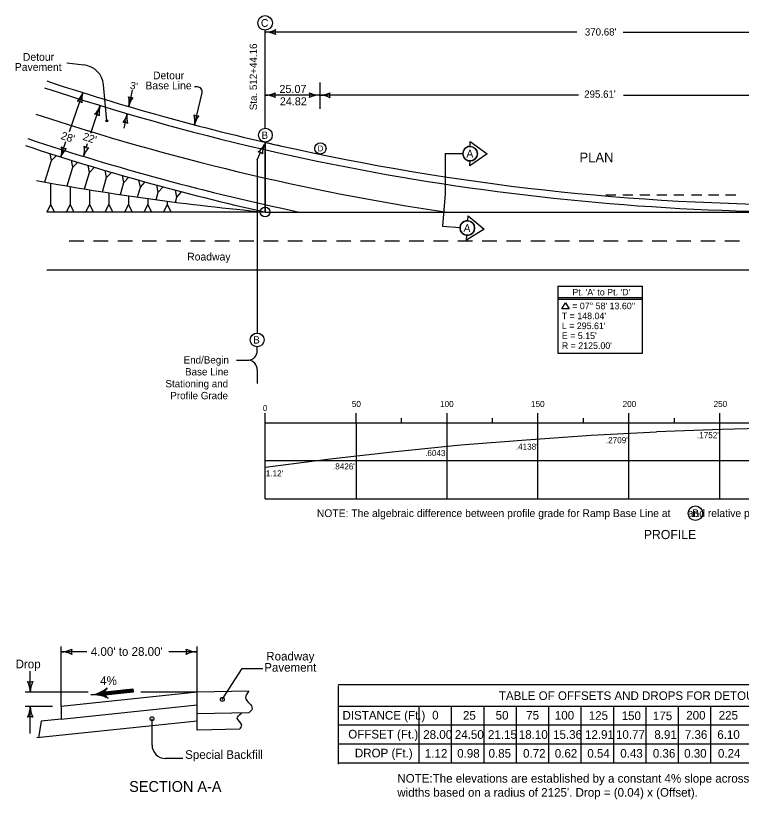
# Model space of a CAD drawing. Extents: x 10133 to 81668, y 4099 to 11018.
# Drawn here: x 13872 to 15616, y 4140 to 6024 of the extents above; entities that cross this region are included whole.
import ezdxf

# ---------------------------------------------------------------- set-up
doc = ezdxf.new("R2010")
doc.units = 0
for name, color, linetype in [('Default', 7, 'Continuous'), ('dsnCellElements', 7, 'Continuous'), ('Level 1', 7, 'Continuous'), ('Level 10', 7, 'Continuous'), ('Level 12', 7, 'Continuous'), ('Level 4', 7, 'Continuous'), ('Level 5', 7, 'Continuous'), ('SheetAddendum', 7, 'Continuous'), ('ShtPlotIdentification', 7, 'Continuous')]:
    doc.layers.add(name, color=color, linetype=linetype)

msp = doc.modelspace()

# ---------------------------------------------------------------- linework, layer by layer
at = {"layer": 'Default'}
for p, q in [((14471.7, 5551.9), (14471.7, 5719.6)), ((14471.7, 5719.6), (14471.7, 5551.9)), ((14471.7, 5551.9), (16078.7, 5551.9)), ((14471.7, 5551.9), (16078.7, 5551.9))]:
    msp.add_line(p, q, dxfattribs=at)
for centre, radius, start, end in [((15786.9, 11406.1), 5836.7, 251.62748, 257.33821), ((15786.9, 11406.1), 5854, 251.62748, 272.85748), ((15786.9, 11406.1), 5920.4, 251.62748, 261.4196), ((15786.9, 11406.1), 5982.7, 251.62748, 258.10097), ((15786.9, 11406.1), 6000.1, 251.62748, 257.33821), ((15786.9, 11406.1), 5836.7, 256.97753, 257.33821), ((15786.9, 11406.1), 5836.7, 257.33821, 270), ((15786.9, 11406.1), 5836.7, 257.33821, 270), ((15002.9, 11433.9), 5905.9, 259.45431, 264.83954)]:
    msp.add_arc(centre, radius, start, end, dxfattribs=at)
at = {"layer": 'dsnCellElements'}
for p, q in [((16087.1, 4415.5), (14647.3, 4415.5)), ((14647.3, 4413.3), (14647.3, 4225.1)), ((16087.1, 4363.6), (14647.3, 4363.6)), ((14841.2, 4363.6), (14841.2, 4227.3)), ((14919, 4363.6), (14919, 4363.6)), ((14919, 4363.6), (14919, 4227.3)), ((14919.3, 4363.6), (14919.3, 4363.6)), ((14919.4, 4363.6), (14919.4, 4363.6)), ((14919.6, 4363.6), (14919.6, 4363.6)), ((14996.9, 4363.6), (14996.9, 4227.3)), ((14996.9, 4363.6), (14996.9, 4363.6)), ((14996.9, 4363.6), (14996.9, 4227.3)), ((14997.1, 4363.6), (14997.1, 4363.6)), ((14997.3, 4363.6), (14997.3, 4363.6)), ((14997.5, 4363.6), (14997.5, 4363.6)), ((15074.8, 4363.6), (15074.8, 4227.3)), ((15152.7, 4363.6), (15152.7, 4227.3)), ((15230.5, 4363.6), (15230.5, 4227.3)), ((15308.4, 4363.6), (15308.4, 4227.3)), ((15386.3, 4363.6), (15386.3, 4227.3)), ((15464.1, 4363.6), (15464.1, 4227.3)), ((15542, 4363.6), (15542, 4227.3)), ((16087.1, 4318.2), (14647.3, 4318.2)), ((16087.1, 4272.8), (14647.3, 4272.8)), ((16087.1, 4227.3), (14647.3, 4227.3))]:
    msp.add_line(p, q, dxfattribs=at)
at = {"layer": 'Level 1'}
for p, q in [((13958.3, 5675.6), (13955.5, 5692.4)), ((13941.9, 5624.1), (13958.3, 5675.6)), ((13958.3, 5675.6), (13970.3, 5687.6)), ((14009.7, 5659.5), (14006.7, 5676.2)), ((14009.7, 5659.5), (14021.6, 5671.6)), ((13995.8, 5614.5), (14009.7, 5659.5)), ((14049.7, 5647.2), (14046.6, 5663.9)), ((14049.7, 5647.2), (14061.5, 5659.4)), ((14090.7, 5635), (14087.5, 5651.7)), ((14037.7, 5607.4), (14049.7, 5647.2)), ((14080.6, 5600.5), (14090.7, 5635)), ((14090.7, 5635), (14102.5, 5647.3)), ((14132.2, 5623), (14128.9, 5639.6)), ((14132.2, 5623), (14143.9, 5635.4)), ((13956.3, 5621.5), (13956.3, 5569.9)), ((14123.9, 5593.8), (14132.2, 5623)), ((14171.8, 5611.8), (14168.3, 5628.5)), ((14171.8, 5611.8), (14183.3, 5624.3)), ((14214.8, 5600), (14211.3, 5616.6)), ((14003, 5613.3), (14003, 5569.9)), ((14049.7, 5605.4), (14049.7, 5569.9)), ((14096.4, 5598), (14096.4, 5569.9)), ((14165, 5587.7), (14171.8, 5611.8)), ((14209.8, 5581.5), (14214.8, 5600)), ((14214.8, 5600), (14226.3, 5612.5)), ((14259.6, 5588), (14255.9, 5604.6)), ((14259.6, 5588), (14271, 5600.7)), ((14143.1, 5590.9), (14143.1, 5569.9)), ((14189.8, 5584.2), (14189.8, 5569.9)), ((14236.5, 5577.9), (14236.5, 5569.9)), ((14256.3, 5575.4), (14259.6, 5588)), ((13956.3, 5569.9), (13946.7, 5551.4)), ((13956.3, 5569.9), (13965.6, 5551.9)), ((14003, 5569.9), (13993.7, 5551.9)), ((14003, 5569.9), (14012.3, 5551.9)), ((14049.7, 5569.9), (14040.4, 5551.9)), ((14049.7, 5569.9), (14059, 5551.9)), ((14096.4, 5569.9), (14086.8, 5551.4)), ((14096.4, 5569.9), (14105.7, 5551.9)), ((14143.1, 5569.9), (14133.8, 5551.9)), ((14143.1, 5569.9), (14152.4, 5551.9)), ((14189.8, 5569.9), (14180.5, 5551.9)), ((14189.8, 5569.9), (14199, 5551.9)), ((14236.5, 5569.9), (14227.2, 5551.9)), ((14236.5, 5569.9), (14245.7, 5551.9))]:
    msp.add_line(p, q, dxfattribs=at)
at = {"layer": 'Level 10'}
for p, q in [((14471.7, 5753.1), (14471.7, 5988.9)), ((14309, 5852.6), (14301.8, 5852.6)), ((14301.8, 5761.5), (14320.3, 5838.1)), ((14471.7, 5719.6), (14471.7, 5720.1)), ((14452.5, 5677.7), (14460.5, 5694.6)), ((14452.5, 5677.7), (14452.5, 5261)), ((15174.7, 5373.4), (15174.7, 5212.7)), ((15174.7, 5373.4), (15378.3, 5373.4)), ((15378.3, 5212.7), (15378.3, 5373.4)), ((15174.7, 5346.3), (15378.3, 5346.3)), ((15174.7, 5342.5), (15378.3, 5342.5)), ((15184.6, 5318.8), (15193.6, 5333.7)), ((15193.6, 5333.7), (15202.5, 5318.8)), ((15202.5, 5318.8), (15184.6, 5318.8)), ((14452.5, 5218.9), (14452.5, 5228)), ((15174.7, 5212.7), (15378.3, 5212.7)), ((14402.5, 5195.7), (14432.1, 5195.7)), ((14452.5, 5172.5), (14452.5, 5139.8)), ((13981.3, 4363.3), (13981.3, 4507.3)), ((14308.1, 4397.5), (14308.1, 4507.3)), ((14199.8, 4333.9), (14199.8, 4270.7)), ((14273.7, 4238.3), (14232.3, 4238.3))]:
    msp.add_line(p, q, dxfattribs=at)
for centre, radius in [((14471.7, 6006.4), 17.5), ((14091.5, 5770.9), 2.42), ((14091.5, 5770.9), 2.05), ((14091.5, 5770.9), 1.71), ((14091.5, 5770.9), 1.32), ((14091.5, 5770.9), 1.05), ((14091.5, 5770.9), 0.874), ((14091.5, 5770.9), 0.683), ((14091.5, 5770.9), 0.505), ((14091.5, 5770.9), 0.313), ((14091.5, 5770.9), 0.149), ((14472.3, 5736.6), 16.5), ((14604.6, 5704.7), 13.4), ((14471.7, 5551.9), 11.7), ((14452.5, 5244.5), 16.5)]:
    msp.add_circle(centre, radius, dxfattribs=at)
for centre, radius, start, end in [((14309, 5840.9), 11.7, 346.4041, 90), ((14152.2, 5844.7), 18.1, 240.459, 275.9257), ((14098.4, 5815.9), 46.8, 348.1924, 16.2649), ((14189.9, 5796.8), 46.8, 140.1199, 168.1924), ((14094.5, 5797.2), 46.8, 320.1199, 348.1924), ((14186, 5778.1), 46.8, 168.1924, 196.2649), ((14310.5, 5802.2), 19.2, 240.2469, 275.7136), ((14253.3, 5771.8), 49.6, 347.9802, 16.0527), ((14350.3, 5751.2), 49.6, 139.9077, 167.9802), ((14132.2, 5749.3), 18.1, 60.459, 95.9257), ((14426.8, 5734.3), 47.3, 306.4802, 334.5527), ((14512.3, 5693.6), 47.3, 154.5527, 182.6252), ((14452.5, 5678.1), 18.3, 46.8193, 82.286), ((14430.5, 5217.6), 22, 274.0563, 3.2919), ((14430.5, 5173.8), 22, 356.7081, 85.9437), ((14232.3, 4270.7), 32.4, 180, 270)]:
    msp.add_arc(centre, radius, start, end, dxfattribs=at)
at = {"layer": 'Level 12'}
for centre in [(14368.8, 4380.5), (14199.8, 4333.9)]:
    msp.add_circle(centre, 4.6, dxfattribs=at)
at = {"layer": 'Level 4'}
for p, q in [((14904.6, 5692.5), (14903.9, 5595.8)), ((14904.6, 5692.5), (14946.6, 5692.2)), ((14903.9, 5595.8), (14898.1, 5517.8)), ((14898.1, 5517.8), (14940, 5514.7))]:
    msp.add_line(p, q, dxfattribs=at)
for points in [[(14964.2, 5709.6), (14964.3, 5721.2), (15004.9, 5691.8), (14963.9, 5662.9), (14964, 5674.6)], [(14964.2, 5709.6), (14964.2, 5709.6), (14964.2, 5709.6)], [(14958.8, 5530.9), (14959.7, 5542.5), (14998.3, 5510.4), (14955.4, 5484.3), (14956.2, 5496)], [(14958.8, 5530.9), (14958.8, 5530.9), (14958.8, 5530.9)]]:
    msp.add_lwpolyline(points, dxfattribs=at)
for centre, radius in [((14964.1, 5692.1), 17.5), ((14957.5, 5513.4), 17.5), ((15505.5, 4827.9), 17.4)]:
    msp.add_circle(centre, radius, dxfattribs=at)
for centre, start, end in [((14964.1, 5692.1), 89.5971, 269.5988), ((14964.1, 5692.1), 269.5988, 89.5971), ((14957.5, 5513.4), 85.783, 265.7846), ((14957.5, 5513.4), 265.7846, 85.783)]:
    msp.add_arc(centre, 17.5, start, end, dxfattribs=at)
at = {"layer": 'Level 5'}
for p, q in [((15314.7, 5592.6), (15290.2, 5592.6)), ((15355.5, 5592.6), (15331, 5592.6)), ((15396.4, 5592.6), (15371.9, 5592.6)), ((15437.2, 5592.6), (15412.7, 5592.6)), ((15478.1, 5592.6), (15453.6, 5592.6)), ((15520.9, 5592.8), (15496.4, 5592.8)), ((15561.7, 5592.8), (15537.2, 5592.8)), ((15602.6, 5592.8), (15578.1, 5592.8)), ((14455.2, 5551.9), (13946.7, 5551.9)), ((14035.9, 5481.9), (14000.8, 5481.9)), ((14094.2, 5481.9), (14059.2, 5481.9)), ((14152.6, 5481.9), (14117.6, 5481.9)), ((14211, 5481.9), (14175.9, 5481.9)), ((14269.3, 5481.9), (14234.3, 5481.9)), ((14327.7, 5481.9), (14292.7, 5481.9)), ((14386.1, 5481.9), (14351, 5481.9)), ((14444.4, 5481.9), (14409.4, 5481.9)), ((14502.8, 5481.9), (14467.8, 5481.9)), ((14561.2, 5481.9), (14526.1, 5481.9)), ((14619.5, 5481.9), (14584.5, 5481.9)), ((14677.9, 5481.9), (14642.9, 5481.9)), ((14736.3, 5481.9), (14701.2, 5481.9)), ((14794.6, 5481.9), (14759.6, 5481.9)), ((14853, 5481.9), (14818, 5481.9)), ((14911.4, 5481.9), (14876.3, 5481.9)), ((14969.7, 5481.9), (14934.7, 5481.9)), ((15028.1, 5481.9), (14993.1, 5481.9)), ((15086.5, 5481.9), (15051.4, 5481.9)), ((15144.8, 5481.9), (15109.8, 5481.9)), ((15203.2, 5481.9), (15168.2, 5481.9)), ((15261.6, 5481.9), (15226.5, 5481.9)), ((15319.9, 5481.9), (15284.9, 5481.9)), ((15378.3, 5481.9), (15343.3, 5481.9)), ((15436.7, 5481.9), (15401.6, 5481.9)), ((15495, 5481.9), (15460, 5481.9)), ((15553.4, 5481.9), (15518.4, 5481.9)), ((15611.8, 5481.9), (15576.7, 5481.9)), ((16078.7, 5411.9), (13947, 5411.9)), ((14471.5, 4862.5), (14471.5, 5068.1)), ((14690.1, 5045.3), (14690.1, 5068.1)), ((14908.7, 4862.5), (14908.7, 5068.1)), ((15127.3, 4862.5), (15127.3, 5068.1)), ((15345.9, 4862.5), (15345.9, 5068.1)), ((15564.5, 4862.5), (15564.5, 5068.1)), ((14799.4, 5045.3), (14799.4, 5056.7)), ((15018, 5045.3), (15018, 5056.7)), ((15236.6, 5045.3), (15236.6, 5056.7)), ((15455.2, 5045.3), (15455.2, 5056.7)), ((14471.5, 5045.3), (16220.3, 5045.3)), ((14690.1, 5045.3), (14690.1, 4862.5)), ((15725.9, 5033), (15569.1, 5029.2)), ((15098.7, 5004.2), (15255.5, 5015.3)), ((15255.5, 5015.3), (15412.3, 5023.7)), ((15569.1, 5029.2), (15412.3, 5023.7)), ((14785.1, 4976.4), (14941.9, 4992.2)), ((14941.9, 4992.2), (15098.7, 5004.2)), ((14628.3, 4958.8), (14785.1, 4976.4)), ((14471.5, 4938.4), (14628.3, 4958.8)), ((16220.3, 4953.9), (14471.5, 4953.9)), ((14471.5, 4862.5), (16220.3, 4862.5)), ((14368.8, 4380.5), (14416.5, 4454.4)), ((14416.5, 4454.4), (14466, 4454.4)), ((14308.1, 4397.5), (13981.3, 4363.3)), ((14432.7, 4400), (14308.1, 4397.5)), ((14308.1, 4306.6), (14308.1, 4397.5)), ((13981.3, 4333), (14308.1, 4367.2)), ((13981.3, 4363.3), (13981.3, 4333)), ((13981.3, 4333), (13933.1, 4328)), ((14432.6, 4348), (14309.1, 4345.6)), ((14308.1, 4328), (13923.3, 4287.8)), ((13933.1, 4328), (13926.8, 4288.2)), ((14410.3, 4308.6), (14309.9, 4306.6))]:
    msp.add_line(p, q, dxfattribs=at)
msp.add_lwpolyline([(14308.1, 4397.5), (13981.3, 4363.3), (13981.3, 4333), (14308.1, 4367.2)], close=True, dxfattribs=at)
for points in [[(14432.7, 4400), (14424.6, 4384.8), (14440.3, 4358.3), (14432.6, 4348)], [(14410.3, 4308.6), (14415.3, 4319.1), (14404.6, 4334.8), (14414.6, 4347.6)]]:
    msp.add_spline(points, degree=3, dxfattribs=at)
at = {"layer": 'SheetAddendum'}
for p, q in [((15221, 5984.3), (14472.9, 5984.3)), ((15331.7, 5984.3), (16079.7, 5984.3)), ((14036.2, 5905.3), (13995.2, 5909.4)), ((14603.7, 5800.2), (14603.7, 5863.4)), ((14091.5, 5770.9), (14083.4, 5857.7)), ((14152.2, 5844.7), (14144.2, 5806.3)), ((14001.8, 5745.3), (14033.3, 5838.7)), ((14536.2, 5832.8), (14472.4, 5832.8)), ((14601.5, 5832.9), (14536.2, 5832.8)), ((15224.4, 5832.6), (14606.5, 5832.6)), ((15333.2, 5832.9), (15786.1, 5833.3)), ((14052.8, 5741.1), (14073, 5801.7)), ((14132.9, 5753.1), (14136.9, 5771.6)), ((13980.8, 5684.3), (13992.7, 5721.1)), ((14041.3, 5705.1), (14045.2, 5717)), ((14043.2, 4494.8), (13981.3, 4494.8)), ((14308.1, 4494.8), (14240.5, 4494.8)), ((13907.3, 4397.5), (13907.3, 4448.4)), ((14046.7, 4397.5), (13895.4, 4397.5)), ((14086.7, 4398.9), (14086.7, 4398.9)), ((14086.9, 4394.8), (14154.4, 4401.8)), ((14087.5, 4390.9), (14087.5, 4390.9)), ((14307.7, 4397.5), (14173, 4397.5)), ((13961.1, 4363.3), (13895.4, 4363.3)), ((13907.3, 4298.7), (13907.3, 4363.3))]:
    msp.add_line(p, q, dxfattribs=at)
for points in [[(14088, 4403.9), (14085.6, 4399), (14086, 4392.2), (14089, 4386.5), (14078.6, 4389.7), (14066.6, 4391.9), (14063.3, 4392.3), (14071.5, 4394.9), (14083.3, 4400.5), (14086.7, 4402.8), (14086.9, 4388.3), (14068.3, 4392.6), (14085.2, 4399.8), (14085.6, 4389.8), (14072.8, 4393.2), (14083.8, 4397.2), (14084.9, 4391.5), (14076.8, 4393.2), (14082.6, 4395.6), (14083.2, 4392.9), (14080.3, 4393.4)], [(14086.7, 4398.7), (14154, 4405.7), (14154.8, 4398), (14087.5, 4390.9), (14087, 4397.6), (14153.2, 4404.8), (14153.7, 4398.6), (14088.9, 4392.1), (14088.2, 4396.7), (14152.4, 4403.6), (14152.7, 4399.5), (14089.6, 4392.9), (14089.2, 4395.8), (14151.7, 4402.7), (14151.9, 4400.4), (14090.4, 4394)]]:
    msp.add_lwpolyline(points, dxfattribs=at)
for centre, radius, start, end in [((14473, 6035.2), 50.9, 270, 298.0725), ((14515.6, 5984.3), 19.7, 162.2666, 197.7334), ((14473, 5933.4), 50.9, 61.9275, 90), ((14030.9, 5852.8), 52.8, 5.3657, 84.2172), ((13986.1, 5854.3), 49.6, 313.6652, 341.7377), ((14080.4, 5823.2), 49.6, 161.7377, 189.8102), ((14472.4, 5882.4), 49.6, 270, 298.0725), ((14472.4, 5783.2), 49.6, 61.9275, 90), ((14514, 5832.8), 19.2, 162.2666, 197.7334), ((14559.9, 5832.9), 19.2, 342.2666, 17.7333), ((14601.5, 5882.5), 49.6, 241.9275, 270), ((14601.5, 5783.3), 49.6, 90, 118.0725), ((14603.7, 5882.2), 49.6, 270, 298.0725), ((14603.7, 5783), 49.6, 61.9275, 90), ((14645.3, 5832.6), 19.2, 162.2666, 197.7334), ((14020.2, 5799.2), 19.2, 54.0044, 89.4711), ((14027.7, 5822.8), 49.6, 313.6652, 341.7377), ((14122, 5791.7), 49.6, 161.7377, 189.8102), ((14061.8, 5767.8), 19.2, 54.0044, 89.4711), ((13933.7, 5699.8), 49.6, 341.7377, 9.8102), ((13993.8, 5723.8), 19.2, 234.0044, 269.4711), ((13987.9, 5701.5), 49.6, 341.7377, 9.8102), ((14048, 5725.4), 19.2, 234.0044, 269.4711), ((14027.9, 5668.7), 49.6, 133.6652, 161.7377), ((14082.1, 5670.4), 49.6, 133.6652, 161.7377), ((13981.3, 4549.9), 55.2, 270, 298.0725), ((13981.3, 4439.6), 55.2, 61.9275, 90), ((14027.5, 4494.8), 21.3, 162.2666, 197.7334), ((14261.8, 4494.8), 21.3, 342.2667, 17.7334), ((14308.1, 4549.9), 55.2, 241.9275, 270), ((14308.1, 4439.6), 55.2, 90, 118.0725), ((13907.3, 4443.7), 21.3, 252.2667, 287.7334), ((13852.2, 4397.5), 55.2, 0, 28.0725), ((13962.5, 4397.5), 55.2, 151.9275, 180), ((13852.2, 4363.3), 55.2, 331.9275, 0), ((13962.5, 4363.3), 55.2, 180, 208.0725), ((13907.3, 4317.1), 21.3, 72.2666, 107.7334)]:
    msp.add_arc(centre, radius, start, end, dxfattribs=at)
for centre, major_axis, start_param, end_param in [((14041.6, 4474.1), (8.7, -83.2), 0.029395, 0.553518), ((14100.9, 4396.2), (-1.5, 14.6), 0.553526, 2.588067), ((14059, 4307.8), (8.7, -83.2), 2.588074, 3.112197)]:
    msp.add_ellipse(centre, major_axis=major_axis, ratio=0.985299, start_param=start_param, end_param=end_param, dxfattribs=at)
at = {"layer": 'ShtPlotIdentification'}
msp.add_line((14471.7, 5551.9), (14455.2, 5551.9), dxfattribs=at)

# ---------------------------------------------------------------- texts
at = {"layer": 'dsnCellElements'}
for s, height, p in [('TABLE OF OFFSETS AND DROPS FOR DETOUR PAVEMENT', 20.766, (15033.3, 4379)), ('DISTANCE (Ft.)', 20.766, (14657.6, 4331.8)), ('0', 20.7, (14873, 4332.2)), ('25', 20.75, (14947, 4331.6)), ('50', 20.75, (15025.6, 4331.9)), ('75', 20.75, (15099.1, 4331.9)), ('100', 20.75, (15167.9, 4331.9)), ('125', 20.75, (15249.4, 4331.3)), ('150', 20.75, (15328.4, 4330.7)), ('200', 20.75, (15483.6, 4331.9)), ('225', 20.75, (15561.6, 4331.9)), ('175', 20.75, (15403.5, 4330.5)), ('OFFSET (Ft.)', 20.766, (14671.4, 4286.4)), ('28.00', 20.75, (14851.6, 4285.6)), ('24.50', 20.75, (14927.6, 4285.6)), ('21.15', 20.75, (15007.1, 4285.6)), ('18.10', 20.75, (15081.3, 4285.6)), ('15.36', 20.75, (15163.6, 4285.6)), ('12.91', 20.75, (15240.4, 4285.6)), ('10.77', 20.75, (15314.7, 4285.6)), ('8.91', 20.75, (15406.9, 4285.6)), ('7.36', 20.75, (15480.2, 4285.6)), ('6.10', 20.75, (15558.2, 4285.6)), ('DROP (Ft.)', 20.77, (14687.3, 4241)), ('1.12', 20.75, (14855.6, 4240.2)), ('0.98', 20.75, (14933.2, 4240.3)), ('0.85', 20.75, (15008.6, 4240.3)), ('0.72', 20.75, (15091.4, 4240.3)), ('0.62', 20.75, (15167.7, 4240.3)), ('0.54', 20.75, (15245.9, 4240.3)), ('0.43', 20.75, (15325.1, 4240.3)), ('0.36', 20.75, (15403.4, 4240.3)), ('0.30', 20.75, (15478.6, 4240.3)), ('0.24', 20.75, (15559.8, 4240.3))]:
    msp.add_text(s, height=height, dxfattribs=at).set_placement(p)
at = {"layer": 'Level 10'}
for s, height, p in [('C', 18.7, (14461.5, 5997)), ("370.68'", 17.43, (15240, 5976.1)), ('Detour ', 18.68, (13889.5, 5915.4)), ('Pavement', 18.68, (13870.2, 5891.2)), ('Detour', 18.68, (14202.2, 5870.9)), ('Base Line', 18.68, (14184, 5846.7)), ('25.07', 19.36, (14506.1, 5838)), ("295.61'", 17.42, (15238.4, 5826.6)), ('24.82', 19.36, (14507, 5808.3)), ('B', 17.6, (14463, 5727.8)), ('D', 14.3, (14598, 5697.5)), ('PLAN', 23.35, (15227.1, 5671.5)), ('Roadway               ', 18.677, (14284.4, 5435.4)), ("Pt. 'A' to Pt. 'D'", 15.889, (15209.9, 5351.3)), ("= 07° 58' 13.60''", 15.889, (15209.5, 5318.3)), ("T = 148.04'", 15.889, (15184.6, 5294.3)), ("L = 295.61'", 15.889, (15184.6, 5270.4)), ("E = 5.15'", 15.89, (15184.6, 5246.6)), ('B', 17.6, (14443.1, 5235.7)), ("R = 2125.00'", 15.889, (15184.6, 5222.8)), ('End/Begin', 17.6, (14275.9, 5187.7)), ('Base Line', 17.6, (14279.3, 5159.1)), ('Stationing and', 17.603, (14232.2, 5130.5)), ('Profile Grade', 17.603, (14243.8, 5101.9)), ('0', 14.6, (14466.3, 5073.4)), ('50', 14.62, (14680.1, 5083.2)), ('100', 14.62, (14892, 5083.2)), ('150', 14.62, (15110.6, 5083.2)), ('200', 14.62, (15330.7, 5083.2)), ('250', 14.62, (15549.3, 5083.2)), (".2709'", 14.62, (15290.6, 4996.2)), (".1752'", 14.62, (15509.3, 5008.2)), (".4138'", 14.62, (15074.1, 4980.6)), ('.6043', 14.62, (14856.1, 4965.2)), (".8426'", 14.62, (14634.7, 4933.1)), ("1.12'", 14.62, (14473.2, 4916.5)), ('NOTE: The algebraic difference between profile grade for Ramp Base Line at      and relative profile grade of Mainline at      is 0.32%. ', 18.5883, (14595.9, 4818.7)), ('B', 18.6, (15497.5, 4818.7)), ('PROFILE', 22, (15381.7, 4765.7)), ('Roadway', 20.77, (14474.4, 4473.9)), ('Pavement', 20.77, (14469.5, 4447)), ('Special Backfill', 20.766, (14279.5, 4237.4)), ('NOTE:The elevations are established by a constant 4% slope across the appropriate detour', 20.766, (14789.3, 4180.2)), ("widths based on a radius of 2125'. Drop = (0.04) x (Offset).", 20.766, (14789.3, 4146.5))]:
    msp.add_text(s, height=height, dxfattribs=at).set_placement(p)
for s, height, rotation, p in [('Sta. 512+44.16', 17.603, 90, (14452.1, 5796.6)), ("3'", 17.6, 348.1924, (14146, 5848.5)), ("28'", 18.68, 341.7377, (13979.4, 5727.9)), ("22'", 18.68, 341.7377, (14031.9, 5725.8))]:
    msp.add_text(s, height=height, rotation=rotation, dxfattribs=at).set_placement(p)
at = {"layer": 'Level 4'}
for rotation, p in [(359.5979, (14955.3, 5682.8)), (355.7838, (14948.1, 5504.7))]:
    msp.add_text('A', height=18.7, rotation=rotation, dxfattribs=at).set_placement(p)
msp.add_text('SECTION A-A', height=25.957, dxfattribs=at).set_placement((14145, 4158.1))
at = {"layer": 'SheetAddendum'}
for s, height, p in [("4.00' to 28.00'", 20.766, (14052.8, 4485.1)), ('Drop', 20.77, (13872.1, 4455.1)), ('4%', 20.77, (14075.2, 4415.1))]:
    msp.add_text(s, height=height, dxfattribs=at).set_placement(p)

doc.saveas('drawing.dxf')
